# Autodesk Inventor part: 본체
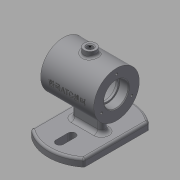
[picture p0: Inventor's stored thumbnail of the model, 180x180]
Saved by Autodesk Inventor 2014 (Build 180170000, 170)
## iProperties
Created: 2017-12
Part Number: 본체
Material: Generic
Document SubType Name: Modeling
Designer: user
Density: 1 g/cm^3
Appearance: Default
Author: user
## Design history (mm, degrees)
sketch "스케치1"
  geometry: L1 (0, 55)-(0, -55); L2 (35, 42.426)-(35, -42.426); L3 (-35, 42.426)-(-35, -42.426); L4 (0, 40)-(0, 24); L5 (-5, 40)-(-5, 24); L6 (5, 24)-(5, 40); L7 (0, 0)-(-16.976, 0); L8 (-5, -40)-(-5, -24); L9 (5, -24)-(5, -40); A1 r 55 centre (0, 0) between (35, 42.426) and (-35, 42.426); A2 r 55 centre (0, 0) between (-35, -42.426) and (35, -42.426); A3 r 5 centre (0, 40) between (5, 40) and (-5, 40); A4 r 5 centre (0, 24) between (-5, 24) and (5, 24); A5 r 5 centre (0, -40) between (-5, -40) and (5, -40); A6 r 5 centre (0, -24) between (5, -24) and (-5, -24); 2 further points
  constraints: 20 end point, 14 point on circle, 6 centre point, 6 symmetric about line, 4 tangent, 3 parallel, 2 coincident, 2 midpoint, 2 point on line, 1 perpendicular, 1 vertical, 2 other
  dimensions: "d2" = 35 distance between parallel lines of L2 L1; "d3" = 35 distance between parallel lines of L3 L1; "d4" = 16 distance of L6.start L6.end; "d5" = 24 distance of point (0, 0) L4.end; "d6" = 5 radius of A3; "d67" = 55 radius of A1
extrude "돌출1" new body sketch "스케치1" distance "d7" = 10; taper "d8" = 0 deg
sketch "스케치2"
  geometry: L1 (-35, 92)-(35, 92); L2 (35, 92)-(35, 62); L3 (35, 62)-(-35, 62); L4 (-35, 62)-(-35, 92); L5 (-35, 0)-(35, 0) reference; 3 further points
  constraints: 8 end point, 2 midpoint, 2 parallel, 2 vertical alignment, 1 horizontal, 1 perpendicular
  dimensions: "d9" = 62 distance between parallel lines of L3 L5; "d10" = 30 distance of L3.end L1.start; "d21" = 70 distance of L1.start L1.end
revolve "회전1" sketch "스케치2" stored, may be unused: angle "d11" = 90 deg
sketch "스케치3"
  geometry: L1 (-15, 0)-(15, 0); L2 (-15, -5)-(15, -5); L3 (15, 5)-(-15, 5); A1 r 5 centre (-15, 0) between (-15, 5) and (-15, -5); A2 r 5 centre (15, 0) between (15, -5) and (15, 5); 1 further point
  constraints: 8 end point, 4 point on circle, 4 tangent, 2 centre point, 1 horizontal, 1 midpoint, 1 parallel
  dimensions: "d12" = 30 distance of L3.start L3.end; "d13" = 5 radius of A1
extrude "돌출2" join sketch "스케치3" stored distance "d14" = 10; taper "d15" = 0 deg
node "작업 평면1"
sketch "스케치4"
  geometry: 1 further point
sketch "스케치5"
  geometry: L1 (35, -30)-(35, 30) reference; L2 (-35, 30)-(35, 30) reference; C1 r 8 at (0, 0); 3 further points
  constraints: 2 midpoint, 1 centre point, 1 horizontal alignment, 1 vertical alignment
  dimensions: "d18" = 35 distance from line of C1.centre L1; "d68" = 16 diameter of C1
extrude "돌출3" join sketch "스케치5" stored distance "d19" = 10; taper "d20" = 0 deg
fillet "모깎기1" dims "d22" = 3
sketch "스케치6"
  geometry: L1 (-35, 32)-(-35, 92) reference; L2 (35, 32)-(35, 92) reference; L3 (-35, 62)-(-23, 62); L4 (-23, 62)-(-23, 78); L5 (-23, 78)-(-35, 78); L6 (-35, 78)-(-35, 62); L7 (-23, 62)-(-20, 62); L8 (-20, 62)-(-20, 76); L9 (-20, 76)-(-23, 76); L10 (-23, 76)-(-23, 62); L11 (-20, 62)-(20, 62); L12 (20, 62)-(20, 87); L13 (20, 87)-(-20, 87); L14 (-20, 87)-(-20, 62); L15 (20, 62)-(23, 62); L16 (23, 62)-(23, 76); L17 (23, 76)-(20, 76); L18 (20, 76)-(20, 62); L19 (23, 62)-(35, 62); L20 (35, 62)-(35, 78); L21 (35, 78)-(23, 78); L22 (23, 78)-(23, 62); 1 further point
  constraints: 40 end point, 10 parallel, 5 horizontal, 5 perpendicular, 3 collinear, 1 midpoint
  dimensions: "d23" = 12 distance of L4.end L5.end; "d24" = 3 distance of L8.end L9.end; "d25" = 3 distance of L16.end L17.end; "d26" = 12 distance of L20.end L21.end; "d27" = 14 distance between parallel lines of L7 L9; "d28" = 16 distance between parallel lines of L3 L5; "d29" = 25 distance between parallel lines of L11 L13
revolve "회전2" sketch "스케치6" stored, may be unused: angle "d30" = 90 deg
fillet "모깎기2" dims "d31" = 3
fillet "모깎기3" dims "d32" = 0.3
chamfer "모따기1" distance "d33" = 1; stored, may be unused: second distance "d34" = 2, angle "d35" = 45 deg
sketch "스케치7"
  geometry: C1 r 4 at (0, 0); 1 further point
  constraints: 1 centre point, 1 coincident
  dimensions: "d36" = 8 diameter of C1
extrude "돌출4" cut sketch "스케치7" stored distance "d37" = 10; taper "d38" = 0 deg
chamfer "모따기2" distance "d39" = 1; stored, may be unused: second distance "d40" = 2, angle "d41" = 45 deg
sketch "스케치8" dims "d42" = 46
  geometry: C1 r 30 at (0, 0) reference; 5 further points
  constraints: 2 vertical alignment, 7 other
  dimensions: "d45" = 360 deg dimension on point (0, 0) point (0, 23) (derived)
hole "구멍1" sketch "스케치8" at (0, 23), (-19.919, -11.5), (19.919, -11.5) diameter "d47" = 3.242; stored, may be unused: countersink angle "d51" = 90 deg, drill point angle "d53" = 118 deg; dims "d48" = 8, "d49" = 4, "d50" = 2, "d52" = 10
fillet "모깎기4" dims "d60" = 5
node "작업 평면3"
sketch "스케치10"
  geometry: L1 (-20, 17)-(-20, 77) reference; L2 (23, 84)-(7, 84) reference; L3 (-20, 77)-(50, 77) reference; 2 further points
  constraints: 1 other
  dimensions: "d62" = 35 distance from line of point (15, 47) L1; "d66" = 30 distance from line of point (15, 47) L3
feature "엠보싱2" sketch "스케치10" dims "d9" = 62, "d10" = 30, "d21" = 70, "d64" = 0.5, "d65" = 0
node "솔리드1"
mirror "대칭1"
other parameters: "d16" = -99
